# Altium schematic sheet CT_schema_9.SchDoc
size 250 x 169 mm
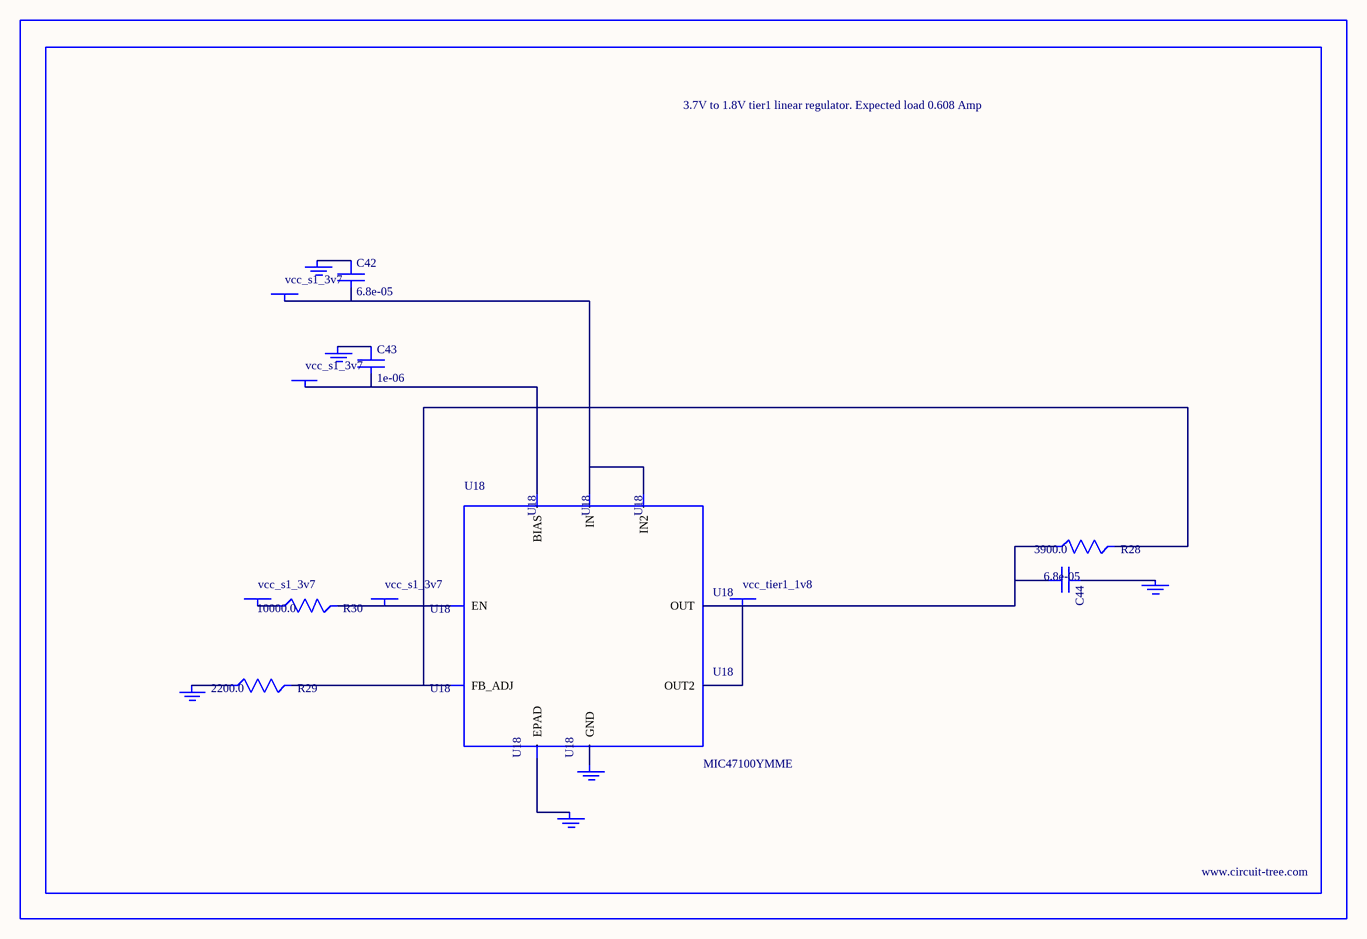
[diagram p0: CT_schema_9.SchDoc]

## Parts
BORDER8  (no value)
C42  6.8e-05  [2220]
C43  1e-06  [C0603]
C44  6.8e-05  [2220]
GND_INSTANCE_8_0  (no value)
GND_INSTANCE_8_1  (no value)
GND_INSTANCE_8_2  (no value)
GND_INSTANCE_8_3  (no value)
GND_INSTANCE_8_4  (no value)
GND_INSTANCE_8_5  (no value)
POWER_INSTANCE_8_0  vcc_s1_3v7
POWER_INSTANCE_8_1  vcc_s1_3v7
POWER_INSTANCE_8_2  vcc_s1_3v7
POWER_INSTANCE_8_3  vcc_s1_3v7
POWER_INSTANCE_8_4  vcc_tier1_1v8
R28  3900.0  [R0603]
R29  2200.0  [R0603]
R30  10000.0  [R0603]
U18  MIC47100YMME  [MSOP-8_EP]

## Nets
NetC42_1: C42.1 GND_INSTANCE_8_0.0(GND)
NetC42_2: C42.2 POWER_INSTANCE_8_0.0(PWR) U18.1(IN) U18.2(IN2)
NetC43_1: C43.1 GND_INSTANCE_8_1.0(GND)
NetC43_2: C43.2 POWER_INSTANCE_8_1.0(PWR) U18.4(BIAS)
NetC44_1: C44.1 GND_INSTANCE_8_3.0(GND)
NetC44_2: C44.2 POWER_INSTANCE_8_4.0(PWR) R28.1 U18.7(OUT) U18.8(OUT2)
NetGND_INSTANCE_8_2_0: GND_INSTANCE_8_2.0(GND) R29.1
NetGND_INSTANCE_8_4_0: GND_INSTANCE_8_4.0(GND) U18.EPAD
NetGND_INSTANCE_8_5_0: GND_INSTANCE_8_5.0(GND) U18.3(GND)
NetPOWER_INSTANCE_8_2_0: POWER_INSTANCE_8_2.0(PWR) R30.1
NetPOWER_INSTANCE_8_3_0: POWER_INSTANCE_8_3.0(PWR) R30.2 U18.5(EN)
NetR28_2: R28.2 R29.2 U18.6(FB_ADJ)

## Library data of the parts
BORDER8 = BORDER_PAGE8
C42 C44 = C5750X5R1A686M
C43 = C0603C105K3RACTU
GND_INSTANCE_8_0-GND_INSTANCE_8_5 = GND
POWER_INSTANCE_8_0-POWER_INSTANCE_8_4 = PWR
R28 = RC0603JR-073K9L
R29 = RC0603JR-072K2L
R30 = RC0603JR-0710KL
